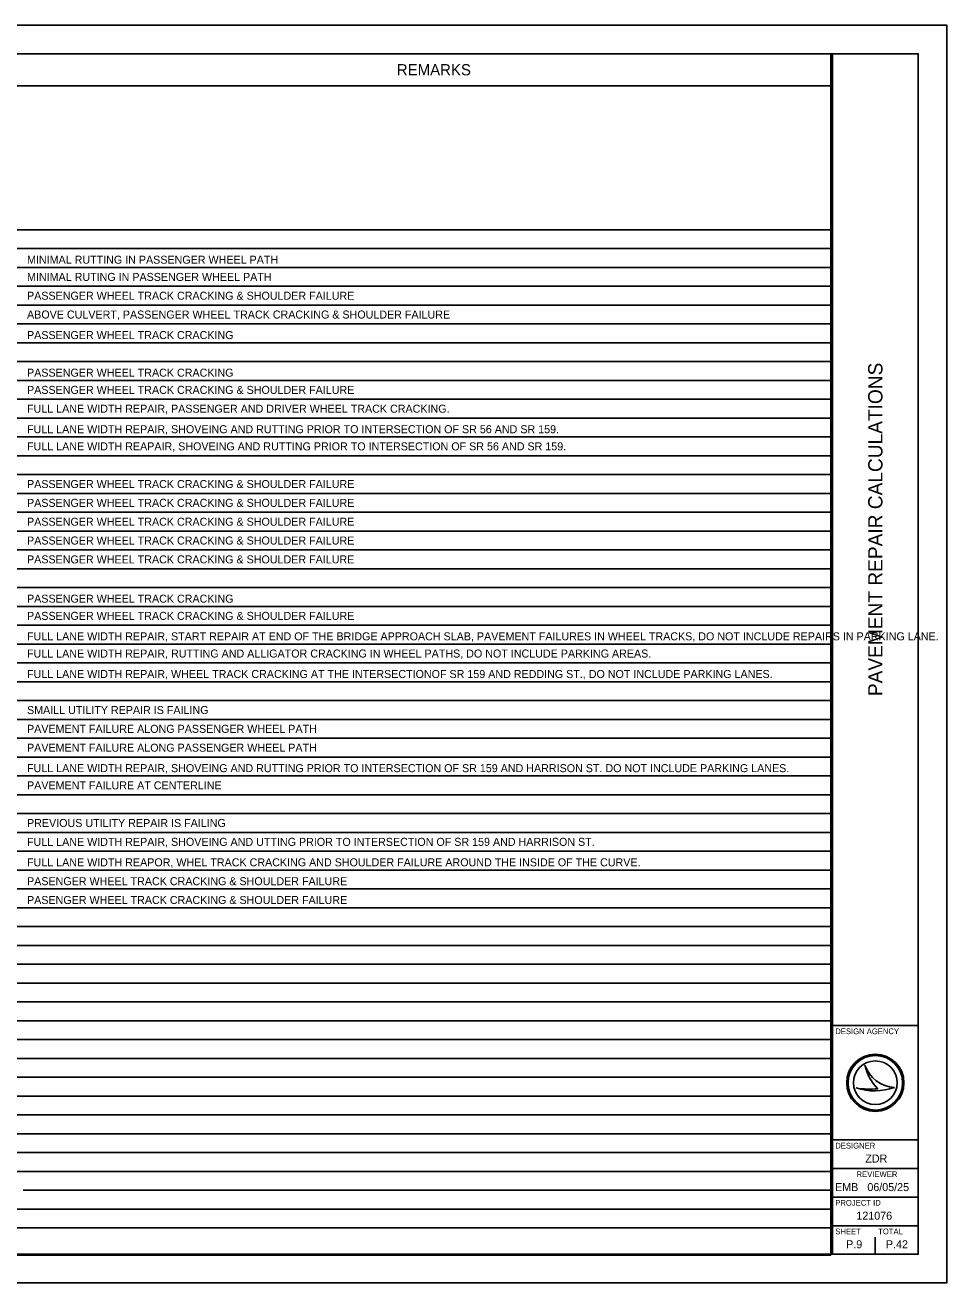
# Model space of a CAD drawing. Extents: x 0 to 66.4, y 0 to 22.
# Drawn here: x 17.89 to 34, y 0 to 22 of the extents above; entities that cross this region are included whole.
import ezdxf

# ---------------------------------------------------------------- set-up
doc = ezdxf.new("R2010")
doc.units = 0
for name, color, linetype in [('Default', 7, 'Continuous'), ('SH_Border', 7, 'Continuous'), ('SH_Cut_Line', 7, 'Continuous'), ('SH_Data', 7, 'Continuous')]:
    doc.layers.add(name, color=color, linetype=linetype)

msp = doc.modelspace()

# ---------------------------------------------------------------- linework, layer by layer
at = {"layer": 'Default'}
for p, q in [((1.5, 21.5), (31.971, 21.5)), ((31.971, 21.5), (31.971, 0.484)), ((1.5, 20.94), (31.971, 20.94)), ((1.5, 18.42), (31.971, 18.42)), ((1.5, 18.091), (31.971, 18.091)), ((1.5, 17.761), (31.971, 17.761)), ((1.5, 17.432), (31.971, 17.432)), ((1.5, 17.102), (31.971, 17.102)), ((1.5, 16.773), (31.971, 16.773)), ((1.5, 16.444), (31.971, 16.444)), ((1.5, 16.114), (31.971, 16.114)), ((1.5, 15.785), (31.971, 15.785)), ((1.5, 15.455), (31.971, 15.455)), ((1.5, 15.126), (31.971, 15.126)), ((1.5, 14.796), (31.971, 14.796)), ((1.5, 14.467), (31.971, 14.467)), ((1.5, 14.138), (31.971, 14.138)), ((1.5, 13.808), (31.971, 13.808)), ((1.5, 13.479), (31.971, 13.479)), ((1.5, 13.149), (31.971, 13.149)), ((1.5, 12.82), (31.971, 12.82)), ((1.5, 12.491), (31.971, 12.491)), ((1.5, 12.161), (31.971, 12.161)), ((1.5, 11.832), (31.971, 11.832)), ((1.5, 11.502), (31.971, 11.502)), ((1.5, 11.173), (31.971, 11.173)), ((1.5, 10.844), (31.971, 10.844)), ((1.5, 10.514), (31.971, 10.514)), ((1.5, 10.185), (31.971, 10.185)), ((1.5, 9.855), (31.971, 9.855)), ((1.5, 9.526), (31.971, 9.526)), ((1.5, 9.196), (31.971, 9.196)), ((1.5, 8.867), (31.971, 8.867)), ((1.5, 8.538), (31.971, 8.538)), ((1.5, 8.208), (31.971, 8.208)), ((1.5, 7.879), (31.971, 7.879)), ((1.5, 7.549), (31.971, 7.549)), ((1.5, 7.22), (31.971, 7.22)), ((1.5, 6.891), (31.971, 6.891)), ((1.5, 6.561), (31.971, 6.561)), ((1.5, 6.232), (31.971, 6.232)), ((1.5, 5.902), (31.971, 5.902)), ((1.5, 5.573), (31.971, 5.573)), ((1.5, 5.244), (31.971, 5.244)), ((1.5, 4.914), (31.971, 4.914)), ((1.5, 4.585), (31.971, 4.585)), ((1.5, 4.255), (31.971, 4.255)), ((1.5, 3.926), (31.971, 3.926)), ((1.5, 3.596), (31.971, 3.596)), ((1.5, 3.267), (31.971, 3.267)), ((1.5, 2.938), (31.971, 2.938)), ((1.5, 2.608), (31.971, 2.608)), ((1.5, 2.279), (31.971, 2.279)), ((1.5, 1.949), (31.971, 1.949)), ((17.855, 1.62), (31.971, 1.62)), ((1.5, 1.291), (31.971, 1.291)), ((1.5, 0.961), (31.971, 0.961)), ((1.5, 0.484), (31.971, 0.484))]:
    msp.add_line(p, q, dxfattribs=at)
at = {"layer": 'SH_Border'}
for p, q in [((32, 0.5), (32, 21.5)), ((32, 4.5), (33.5, 4.5)), ((32, 2.5), (33.5, 2.5)), ((32, 2), (33.5, 2)), ((32, 1.5), (33.5, 1.5)), ((32, 1), (33.5, 1))]:
    msp.add_line(p, q, dxfattribs=at)
msp.add_lwpolyline([(1.5, 21.5), (33.5, 21.5), (33.5, 0.5), (1.5, 0.5)], close=True, dxfattribs=at)
at = {"layer": 'SH_Cut_Line'}
msp.add_lwpolyline([(0, 0), (34, 0), (34, 22), (0, 22)], close=True, dxfattribs=at)
at = {"layer": 'SH_Data'}
for p, q in [((32.567, 3.81), (32.567, 3.81)), ((32.417, 3.41), (32.417, 3.41)), ((32.75, 3.5), (32.75, 3.5)), ((33.087, 3.419), (33.087, 3.419)), ((32.375, 0.675), (32.375, 0.675)), ((32.75, 0.5), (32.75, 0.8))]:
    msp.add_line(p, q, dxfattribs=at)
for radius in [0.5, 0.477, 0.477, 0.382]:
    msp.add_circle((32.75, 3.5), radius, dxfattribs=at)
for centre, radius, start, end in [((33.116, 3.998), 0.58, 198.9257, 198.9319), ((33.347, 3.97), 0.796, 191.6379, 191.6421), ((33.116, 3.998), 0.58, 198.9319, 267.1657), ((33.347, 3.97), 0.796, 191.6421, 226.0947), ((32.739, 4.37), 1.013, 251.4576, 290.0832), ((32.648, 4.654), 1.266, 259.4964, 259.4995), ((32.739, 4.37), 1.013, 251.4527, 251.4576), ((32.648, 4.654), 1.266, 259.4995, 276.6672)]:
    msp.add_arc(centre, radius, start, end, dxfattribs=at)

# ---------------------------------------------------------------- texts
at = {"layer": 'Default'}
for s, height, p in [('REMARKS', 0.196, (24.385, 21.122)), ('MINIMAL RUTTING IN PASSENGER WHEEL PATH', 0.14, (17.921, 17.827)), ('MINIMAL RUTING IN PASSENGER WHEEL PATH', 0.14, (17.921, 17.526)), ('PASSENGER WHEEL TRACK CRACKING & SHOULDER FAILURE', 0.14, (17.921, 17.197)), ('ABOVE CULVERT, PASSENGER WHEEL TRACK CRACKING & SHOULDER FAILURE', 0.14, (17.921, 16.868)), ('PASSENGER WHEEL TRACK CRACKING', 0.14, (17.921, 16.509)), ('PASSENGER WHEEL TRACK CRACKING', 0.14, (17.921, 15.851)), ('PASSENGER WHEEL TRACK CRACKING & SHOULDER FAILURE', 0.14, (17.921, 15.55)), ('FULL LANE WIDTH REPAIR, PASSENGER AND DRIVER WHEEL TRACK CRACKING.', 0.14, (17.921, 15.221)), ('FULL LANE WIDTH REPAIR, SHOVEING AND RUTTING PRIOR TO INTERSECTION OF SR 56 AND SR 159.', 0.14, (17.921, 14.862)), ('FULL LANE WIDTH REAPAIR, SHOVEING AND RUTTING PRIOR TO INTERSECTION OF SR 56 AND SR 159.', 0.14, (17.921, 14.562)), ('PASSENGER WHEEL TRACK CRACKING & SHOULDER FAILURE', 0.14, (17.921, 13.903)), ('PASSENGER WHEEL TRACK CRACKING & SHOULDER FAILURE', 0.14, (17.921, 13.574)), ('PASSENGER WHEEL TRACK CRACKING & SHOULDER FAILURE', 0.14, (17.921, 13.244)), ('PASSENGER WHEEL TRACK CRACKING & SHOULDER FAILURE', 0.14, (17.921, 12.915)), ('PASSENGER WHEEL TRACK CRACKING & SHOULDER FAILURE', 0.14, (17.921, 12.585)), ('PASSENGER WHEEL TRACK CRACKING', 0.14, (17.921, 11.898)), ('PASSENGER WHEEL TRACK CRACKING & SHOULDER FAILURE', 0.14, (17.921, 11.597)), ('FULL LANE WIDTH REPAIR, START REPAIR AT END OF THE BRIDGE APPROACH SLAB, PAVEMENT FAILURES IN WHEEL TRACKS, DO NOT INCLUDE REPAIRS IN PARKING LANE.', 0.14, (17.921, 11.239)), ('FULL LANE WIDTH REPAIR, RUTTING AND ALLIGATOR CRACKING IN WHEEL PATHS, DO NOT INCLUDE PARKING AREAS.', 0.14, (17.921, 10.938)), ('FULL LANE WIDTH REPAIR, WHEEL TRACK CRACKING AT THE INTERSECTIONOF SR 159 AND REDDING ST., DO NOT INCLUDE PARKING LANES.', 0.14, (17.921, 10.58)), ('SMAILL UTILITY REPAIR IS FAILING', 0.14, (17.921, 9.95)), ('PAVEMENT FAILURE ALONG PASSENGER WHEEL PATH', 0.14, (17.921, 9.621)), ('PAVEMENT FAILURE ALONG PASSENGER WHEEL PATH', 0.14, (17.921, 9.291)), ('FULL LANE WIDTH REPAIR, SHOVEING AND RUTTING PRIOR TO INTERSECTION OF SR 159 AND HARRISON ST. DO NOT INCLUDE PARKING LANES.', 0.14, (17.921, 8.933)), ('PAVEMENT FAILURE AT CENTERLINE', 0.14, (17.921, 8.632)), ('PREVIOUS UTILITY REPAIR IS FAILING', 0.14, (17.921, 7.974)), ('FULL LANE WIDTH REPAIR, SHOVEING AND UTTING PRIOR TO INTERSECTION OF SR 159 AND HARRISON ST.', 0.14, (17.921, 7.644)), ('FULL LANE WIDTH REAPOR, WHEL TRACK CRACKING AND SHOULDER FAILURE AROUND THE INSIDE OF THE CURVE.', 0.14, (17.921, 7.286)), ('PASENGER WHEEL TRACK CRACKING & SHOULDER FAILURE', 0.14, (17.921, 6.956)), ('PASENGER WHEEL TRACK CRACKING & SHOULDER FAILURE', 0.14, (17.921, 6.627))]:
    msp.add_text(s, height=height, dxfattribs=at).set_placement(p)
at = {"layer": 'SH_Data'}
msp.add_text('PAVEMENT REPAIR CALCULATIONS', height=0.25, rotation=90, dxfattribs=at).set_placement((32.875, 10.263))
for s, height, p in [('DESIGN AGENCY', 0.1, (32.05, 4.35)), ('DESIGNER', 0.1, (32.05, 2.35)), ('ZDR', 0.14, (32.575, 2.105)), ('REVIEWER', 0.1, (32.422, 1.85)), ('EMB', 0.14, (32.047, 1.605)), ('06/05/25', 0.14, (32.611, 1.605)), ('PROJECT ID', 0.1, (32.05, 1.35)), ('121076', 0.14, (32.419, 1.105)), ('SHEET', 0.1, (32.05, 0.85)), ('TOTAL', 0.1, (32.8, 0.85)), ('P.9', 0.14, (32.24, 0.605)), ('P.42', 0.14, (32.935, 0.605))]:
    msp.add_text(s, height=height, dxfattribs=at).set_placement(p)

doc.saveas('drawing.dxf')
